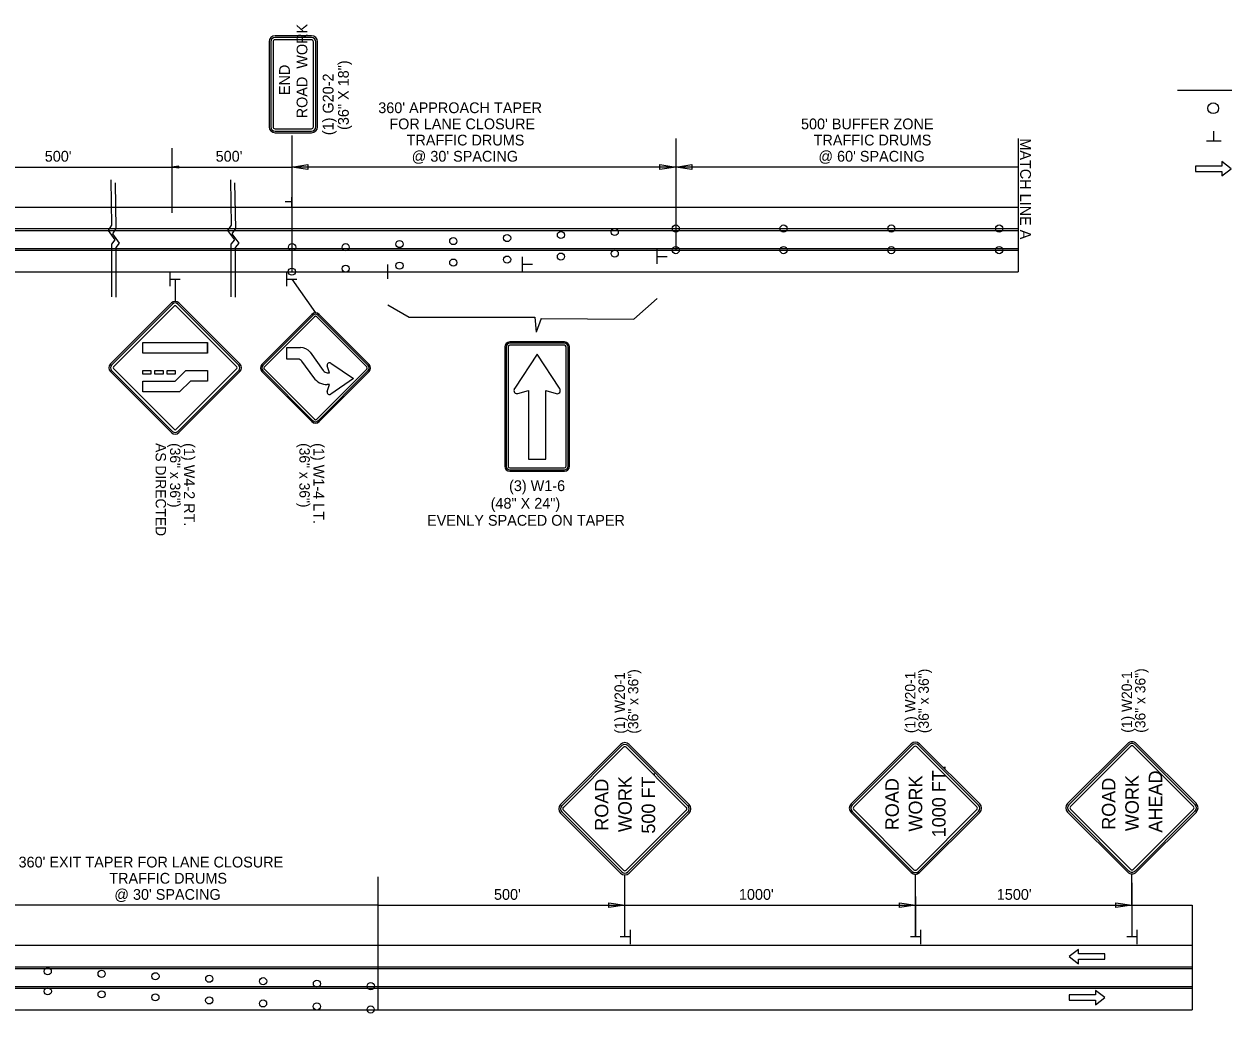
# Model space of a CAD drawing. Extents: x 1930579 to 1946213, y 596452 to 597784.
# Drawn here: x 1936788 to 1937455, y 597094 to 597644 of the extents above; entities that cross this region are included whole.
import ezdxf

# ---------------------------------------------------------------- set-up
doc = ezdxf.new("R2010")
doc.units = 0
for name, color, linetype in [('Default', 7, 'Continuous'), ('P_TC_Signs_Permanent', 7, 'Continuous'), ('P_TC_Signs_Temporary', 7, 'Continuous'), ('R_Border', 7, 'Continuous'), ('R_MOT', 7, 'Continuous'), ('R_Striping', 7, 'Continuous')]:
    doc.layers.add(name, color=color, linetype=linetype)

# ---------------------------------------------------------------- blocks, each defined once
blk = doc.blocks.new('W20-1')
at = {"layer": 'P_TC_Signs_Temporary'}
for p, q in [((-5.97, 6.53), (-0.4, 12.1)), ((-5.86, 6.42), (-0.29, 11.99)), ((-5.7, 6.26), (-0.13, 11.83)), ((0.13, 11.83), (5.7, 6.26)), ((0.29, 11.99), (5.86, 6.42)), ((0.4, 12.1), (5.97, 6.53)), ((-0.4, 0.16), (-5.97, 5.73)), ((-0.29, 0.28), (-5.86, 5.84)), ((-0.13, 0.43), (-5.7, 6)), ((5.7, 6), (0.13, 0.43)), ((5.86, 5.84), (0.29, 0.28)), ((5.97, 5.73), (0.4, 0.16))]:
    blk.add_line(p, q, dxfattribs=at)
for centre, radius, start, end in [((0, 11.7), 0.562, 45, 135), ((0, 11.7), 0.406, 45, 135), ((0, 11.7), 0.188, 45, 135), ((-5.57, 6.13), 0.562, 135, 225), ((-5.57, 6.13), 0.406, 135, 225), ((-5.57, 6.13), 0.187, 135, 225), ((5.57, 6.13), 0.187, 315, 45), ((5.57, 6.13), 0.406, 315, 45), ((5.57, 6.13), 0.562, 315, 45), ((0, 0.56), 0.562, 225, 315), ((0, 0.56), 0.406, 225, 315), ((0, 0.56), 0.188, 225, 315)]:
    blk.add_arc(centre, radius, start, end, dxfattribs=at)
for s, p in [(' ROAD ', (-2.5, 7.67)), ('WORK', (-2.16, 5.5)), (' AHEAD ', (-2.76, 3.33))]:
    blk.add_text(s, height=1.25, dxfattribs=at).set_placement(p)

msp = doc.modelspace()

# ---------------------------------------------------------------- linework, layer by layer
at = {"layer": 'Default'}
for p, q in [((1937150.32, 597580.59), (1937150.32, 597518.47)), ((1937340.86, 597580.59), (1937340.86, 597506.47)), ((1936869.84, 597575.24), (1936869.84, 597539.32)), ((1936936.62, 597575.24), (1936936.62, 597506.47)), ((1936749.27, 597564.71), (1936936.62, 597564.71)), ((1936873.67, 597565.28), (1936869.84, 597564.71)), ((1936869.84, 597564.71), (1936936.62, 597564.71)), ((1936873.67, 597564.13), (1936869.84, 597564.71)), ((1936873.67, 597565.19), (1936870.48, 597564.71)), ((1936873.67, 597564.23), (1936870.48, 597564.71)), ((1936873.67, 597565.09), (1936871.14, 597564.71)), ((1936873.67, 597564.33), (1936871.14, 597564.71)), ((1936873.67, 597564.99), (1936871.77, 597564.71)), ((1936873.67, 597564.42), (1936871.77, 597564.71)), ((1936873.67, 597564.89), (1936872.42, 597564.71)), ((1936873.67, 597564.52), (1936872.42, 597564.71)), ((1936873.67, 597564.8), (1936873.06, 597564.71)), ((1936873.67, 597564.62), (1936873.06, 597564.71)), ((1936873.67, 597564.13), (1936873.67, 597565.28)), ((1936936.62, 597564.71), (1936945.49, 597566.04)), ((1937303.84, 597564.71), (1936936.62, 597564.71)), ((1936945.49, 597563.38), (1936936.62, 597564.71)), ((1936945.49, 597566.04), (1936945.49, 597563.38)), ((1937141.45, 597563.38), (1937141.45, 597566.04)), ((1937141.45, 597566.04), (1937150.32, 597564.71)), ((1937150.32, 597564.71), (1937141.45, 597563.38)), ((1937150.32, 597564.71), (1937159.19, 597566.04)), ((1937159.19, 597563.38), (1937150.32, 597564.71)), ((1937159.19, 597566.04), (1937159.19, 597563.38)), ((1937340.86, 597564.71), (1937303.84, 597564.71)), ((1936936.54, 597545.34), (1936932.94, 597545.34)), ((1936936.62, 597542.72), (1936936.62, 597548)), ((1936407.68, 597542.47), (1937340.86, 597542.47)), ((1936407.68, 597530.47), (1937340.86, 597530.47)), ((1936407.68, 597529.47), (1937340.86, 597529.47)), ((1936407.68, 597519.47), (1937340.86, 597519.47)), ((1936407.68, 597518.47), (1937340.86, 597518.47)), ((1937139.89, 597510.89), (1937139.89, 597518.87)), ((1936990.13, 597502.48), (1936990.13, 597510.46)), ((1937065.01, 597506.69), (1937065.01, 597514.67)), ((1937065.13, 597510.66), (1937070.58, 597510.66)), ((1937140.01, 597514.86), (1937145.46, 597514.86)), ((1936407.68, 597506.47), (1937340.86, 597506.47)), ((1936868.85, 597498.34), (1936868.85, 597506.32)), ((1936933.78, 597498.34), (1936933.78, 597506.32)), ((1936990.25, 597506.45), (1936995.69, 597506.45)), ((1936868.97, 597502.31), (1936874.41, 597502.31)), ((1936933.9, 597502.31), (1936939.34, 597502.31)), ((1936984.52, 597169.77), (1936984.52, 597095.65)), ((1937404.18, 597166.28), (1937404.18, 597136.25)), ((1937283.73, 597158.78), (1937283.73, 597136.25)), ((1936984.52, 597153.89), (1936770.82, 597153.89)), ((1936984.52, 597153.89), (1937437.73, 597153.89)), ((1937113.15, 597152.56), (1937113.15, 597155.22)), ((1937113.15, 597155.22), (1937122.01, 597153.89)), ((1937122.01, 597153.89), (1937113.15, 597152.56)), ((1937274.86, 597152.56), (1937274.86, 597155.22)), ((1937274.86, 597155.22), (1937283.73, 597153.89)), ((1937283.73, 597153.89), (1937274.86, 597152.56)), ((1937395.31, 597152.56), (1937395.31, 597155.22)), ((1937395.31, 597155.22), (1937404.18, 597153.89)), ((1937404.18, 597153.89), (1937395.31, 597152.56)), ((1937437.73, 597153.89), (1937437.73, 597095.65)), ((1937124.76, 597136.27), (1937119.32, 597136.26)), ((1937124.88, 597140.24), (1937124.88, 597132.26)), ((1937286.33, 597136.31), (1937280.88, 597136.31)), ((1937286.45, 597140.28), (1937286.45, 597132.3)), ((1937406.79, 597136.27), (1937401.34, 597136.27)), ((1937406.9, 597140.24), (1937406.9, 597132.26)), ((1936437.73, 597131.65), (1937437.73, 597131.65)), ((1936437.73, 597119.65), (1937437.73, 597119.65)), ((1936437.73, 597119.65), (1936984.52, 597119.65)), ((1936437.73, 597118.65), (1937437.73, 597118.65)), ((1936437.73, 597108.65), (1937437.73, 597108.65)), ((1936437.73, 597107.65), (1937437.73, 597107.65)), ((1936437.73, 597095.65), (1937437.73, 597095.65))]:
    msp.add_line(p, q, dxfattribs=at)
for points in [[(1936835.94, 597557.58), (1936836.33, 597532.34), (1936834.38, 597529.45), (1936838.17, 597524.25), (1936836.18, 597521.85), (1936836.17, 597492.5)], [(1936902.4, 597557.58), (1936902.78, 597532.34), (1936900.83, 597529.45), (1936904.63, 597524.25), (1936902.63, 597521.85), (1936902.63, 597492.5)], [(1936838.33, 597555.98), (1936838.72, 597530.42), (1936836.77, 597527.52), (1936840.57, 597522.32), (1936838.57, 597519.92), (1936838.57, 597492.36)], [(1936904.79, 597555.98), (1936905.18, 597530.42), (1936903.23, 597527.52), (1936907.03, 597522.32), (1936905.03, 597519.92), (1936905.02, 597492.36)]]:
    msp.add_lwpolyline(points, dxfattribs=at)
for centre, radius in [((1937449.45, 597597.42), 3), ((1937116.34, 597528.57), 1.99), ((1937150.32, 597530.47), 1.99), ((1937210.32, 597530.47), 1.99), ((1937270.32, 597530.47), 1.99), ((1937330.32, 597530.47), 1.99), ((1936996.53, 597521.84), 1.99), ((1937026.48, 597523.52), 1.99), ((1937056.43, 597525.2), 1.99), ((1937086.39, 597526.88), 1.99), ((1936936.78, 597520.13), 1.99), ((1936966.57, 597520.16), 1.99), ((1937086.39, 597514.88), 1.99), ((1937116.34, 597516.57), 1.99), ((1937150.32, 597518.47), 1.99), ((1937210.32, 597518.47), 1.99), ((1937270.32, 597518.47), 1.99), ((1937330.32, 597518.47), 1.99), ((1936966.57, 597508.16), 1.99), ((1936996.53, 597509.84), 1.99), ((1937026.48, 597511.52), 1.99), ((1937056.43, 597513.2), 1.99), ((1936936.62, 597506.47), 1.99), ((1936800.75, 597117.08), 1.99), ((1936830.72, 597115.71), 1.99), ((1936860.69, 597114.34), 1.99), ((1936890.66, 597112.97), 1.99), ((1936920.63, 597111.59), 1.99), ((1936950.59, 597110.22), 1.99), ((1936980.56, 597108.85), 1.99), ((1936800.78, 597105.97), 1.99), ((1936830.73, 597104.29), 1.99), ((1936860.68, 597102.61), 1.99), ((1936890.64, 597100.93), 1.99), ((1936920.59, 597099.24), 1.99), ((1936950.54, 597097.56), 1.99), ((1936980.49, 597095.88), 1.99)]:
    msp.add_circle(centre, radius, dxfattribs=at)
at = {"layer": 'P_TC_Signs_Permanent'}
for p, q in [((1936835.63, 597455.14), (1936869.57, 597489.08)), ((1936919.98, 597454.85), (1936947.82, 597482.69)), ((1936920.51, 597454.32), (1936948.35, 597482.16)), ((1936949.15, 597481.36), (1936921.31, 597453.52)), ((1936978.32, 597453.52), (1936950.47, 597481.36)), ((1936951.27, 597482.16), (1936979.11, 597454.32)), ((1936951.8, 597482.69), (1936979.64, 597454.85)), ((1936889.69, 597461.06), (1936889.69, 597467.06)), ((1937055.13, 597464.56), (1937055.13, 597398.19)), ((1937055.88, 597464.56), (1937055.88, 597398.19)), ((1937057.01, 597464.56), (1937057.01, 597398.19)), ((1937088.32, 597467.38), (1937057.95, 597467.38)), ((1937088.32, 597466.63), (1937057.95, 597466.63)), ((1937088.32, 597465.5), (1937057.95, 597465.5)), ((1937089.26, 597398.19), (1937089.26, 597464.56)), ((1937090.38, 597398.19), (1937090.38, 597464.56)), ((1937091.13, 597398.19), (1937091.13, 597464.56)), ((1936948.77, 597447.57), (1936942.25, 597456.61)), ((1936946.73, 597461.62), (1936954.09, 597451.4)), ((1936869.57, 597416.95), (1936835.63, 597450.9)), ((1936907.75, 597450.9), (1936873.81, 597416.95)), ((1936947.82, 597423.03), (1936919.98, 597450.87)), ((1936948.35, 597423.56), (1936920.51, 597451.4)), ((1936921.31, 597452.2), (1936949.15, 597424.35)), ((1936950.47, 597424.35), (1936978.32, 597452.2)), ((1936979.11, 597451.4), (1936951.27, 597423.56)), ((1936979.64, 597450.87), (1936951.8, 597423.03)), ((1937057.95, 597397.25), (1937088.32, 597397.25)), ((1937057.95, 597396.13), (1937088.32, 597396.13)), ((1937057.95, 597395.38), (1937088.32, 597395.38))]:
    msp.add_line(p, q, dxfattribs=at)
for points in [[(1936870.2, 597488.44), (1936836.26, 597454.5)], [(1936837.32, 597453.44), (1936871.26, 597487.38)], [(1936872.11, 597487.38), (1936906.05, 597453.44)], [(1936907.11, 597454.5), (1936873.17, 597488.44)], [(1936873.81, 597489.08), (1936890.78, 597472.11), (1936907.75, 597455.14)], [(1936939.97, 597457.78), (1936933.87, 597457.78), (1936933.87, 597464.34), (1936941.41, 597464.34)], [(1937085.58, 597441.63), (1937073.13, 597460.63), (1937060.73, 597441.62)], [(1936836.26, 597451.53), (1936870.2, 597417.59)], [(1936871.26, 597418.65), (1936837.32, 597452.59)], [(1936906.05, 597452.59), (1936872.11, 597418.65)], [(1936873.17, 597417.59), (1936907.11, 597451.53)], [(1936956.37, 597450.23), (1936957.57, 597450.23), (1936956.34, 597454.05)], [(1936958.33, 597455.54), (1936970.91, 597446.95), (1936958.33, 597438.37)], [(1936956.34, 597439.85), (1936957.57, 597443.67), (1936956.37, 597443.67)], [(1937062.5, 597438.67), (1937068.26, 597440.39), (1937068.26, 597402.13), (1937078.01, 597402.13), (1937078.01, 597440.39), (1937083.76, 597438.64)]]:
    msp.add_lwpolyline(points, dxfattribs=at)
for points in [[(1936853.69, 597461.06), (1936853.69, 597467.06), (1936889.69, 597467.06), (1936889.69, 597461.06)], [(1936853.69, 597449.42), (1936853.69, 597451.52), (1936858.19, 597451.52), (1936858.19, 597449.42)], [(1936853.69, 597439.52), (1936853.69, 597445.52), (1936871.69, 597445.52), (1936877.69, 597451.52), (1936889.69, 597451.52), (1936889.69, 597445.52), (1936880.17, 597445.52), (1936874.17, 597439.52)], [(1936860.44, 597449.42), (1936860.44, 597451.52), (1936864.94, 597451.52), (1936864.94, 597449.42)], [(1936867.19, 597449.42), (1936867.19, 597451.52), (1936871.69, 597451.52), (1936871.69, 597449.42)]]:
    msp.add_lwpolyline(points, close=True, dxfattribs=at)
for centre, radius, start, end in [((1936871.69, 597486.96), 3, 45, 135), ((1936871.69, 597486.96), 2.1, 45, 135), ((1936871.69, 597486.96), 0.6, 45, 135), ((1936949.81, 597480.7), 2.81, 45, 135), ((1936949.81, 597480.7), 2.06, 45, 135), ((1936949.81, 597480.7), 0.938, 45, 135), ((1936941.41, 597457.78), 6.56, 35.77329, 90), ((1937057.95, 597464.56), 2.81, 90, 180), ((1937057.95, 597464.56), 2.06, 90, 180), ((1937057.95, 597464.56), 0.938, 90, 180), ((1937088.32, 597464.56), 2.81, 360, 90), ((1937088.32, 597464.56), 2.06, 360, 90), ((1937088.32, 597464.56), 0.938, 360, 90), ((1936939.97, 597454.97), 2.81, 35.77329, 90), ((1936837.75, 597453.02), 3, 135, 225), ((1936837.75, 597453.02), 2.1, 135, 225), ((1936837.75, 597453.02), 0.6, 135, 225), ((1936905.63, 597453.02), 0.6, 315, 45), ((1936905.63, 597453.02), 2.1, 315, 45), ((1936905.63, 597453.02), 3, 315, 45), ((1936921.97, 597452.86), 2.81, 135, 225), ((1936921.97, 597452.86), 2.06, 135, 225), ((1936921.97, 597452.86), 0.937, 135, 225), ((1936956.37, 597453.05), 2.81, 215.77329, 270), ((1936957.59, 597454.45), 1.31, 55.6763, 197.81282), ((1936977.65, 597452.86), 0.938, 315, 45), ((1936977.65, 597452.86), 2.06, 315, 45), ((1936977.65, 597452.86), 2.81, 315, 45), ((1936956.37, 597453.05), 9.38, 215.77329, 270), ((1936957.59, 597439.45), 1.31, 162.18718, 304.3237), ((1937062.01, 597440.37), 1.76, 146.59943, 285.96908), ((1936997.93, 597482.63), 75, 326.59943, 326.85697), ((1937084.25, 597440.37), 1.8, 254.03093, 33.47548), ((1937148.31, 597482.73), 75, 213.2286, 213.47548), ((1936949.81, 597425.02), 2.06, 225, 315), ((1936949.81, 597425.02), 0.938, 225, 315), ((1936871.69, 597419.08), 3, 225, 315), ((1936871.69, 597419.08), 2.1, 225, 315), ((1936871.69, 597419.08), 0.6, 225, 315), ((1936949.81, 597425.02), 2.81, 225, 315), ((1937057.95, 597398.19), 2.81, 180, 270), ((1937057.95, 597398.19), 2.06, 180, 270), ((1937057.95, 597398.19), 0.937, 180, 270), ((1937088.32, 597398.19), 2.81, 270, 360), ((1937088.32, 597398.19), 2.06, 270, 360), ((1937088.32, 597398.19), 0.938, 270, 360)]:
    msp.add_arc(centre, radius, start, end, dxfattribs=at)
at = {"layer": 'P_TC_Signs_Temporary'}
for p, q in [((1936947.54, 597637.78), (1936927.29, 597637.78)), ((1936947.54, 597636.84), (1936927.29, 597636.84)), ((1936923.92, 597634.41), (1936923.92, 597587.16)), ((1936924.85, 597634.41), (1936924.85, 597587.16)), ((1936926.17, 597634.41), (1936926.17, 597587.16)), ((1936947.54, 597635.53), (1936927.29, 597635.53)), ((1936948.67, 597587.16), (1936948.67, 597634.41)), ((1936949.98, 597587.16), (1936949.98, 597634.41)), ((1936950.92, 597587.16), (1936950.92, 597634.41)), ((1936927.29, 597586.03), (1936947.54, 597586.03)), ((1936927.29, 597584.72), (1936947.54, 597584.72)), ((1936927.29, 597583.78), (1936947.54, 597583.78)), ((1937086.19, 597209.95), (1937119.6, 597243.37)), ((1937124.37, 597243.37), (1937157.78, 597209.95)), ((1937247.88, 597210.25), (1937281.29, 597243.66)), ((1937248.54, 597209.59), (1937281.95, 597243)), ((1937285.4, 597243), (1937318.81, 597209.59)), ((1937286.06, 597243.66), (1937319.48, 597210.25)), ((1937086.85, 597209.29), (1937120.26, 597242.7)), ((1937087.78, 597208.36), (1937121.19, 597241.77)), ((1937122.78, 597241.77), (1937156.19, 597208.36)), ((1937123.71, 597242.7), (1937157.12, 597209.29)), ((1937249.47, 597208.66), (1937282.88, 597242.07)), ((1937284.47, 597242.07), (1937317.88, 597208.66)), ((1937119.6, 597171.77), (1937086.19, 597205.18)), ((1937120.26, 597172.43), (1937086.85, 597205.84)), ((1937121.19, 597173.36), (1937087.78, 597206.77)), ((1937156.19, 597206.77), (1937122.78, 597173.36)), ((1937157.12, 597205.84), (1937123.71, 597172.43)), ((1937157.78, 597205.18), (1937124.37, 597171.77)), ((1937281.29, 597172.07), (1937247.88, 597205.48)), ((1937281.95, 597172.73), (1937248.54, 597206.14)), ((1937282.88, 597173.66), (1937249.47, 597207.07)), ((1937317.88, 597207.07), (1937284.47, 597173.66)), ((1937318.81, 597206.14), (1937285.4, 597172.73)), ((1937319.48, 597205.48), (1937286.06, 597172.07))]:
    msp.add_line(p, q, dxfattribs=at)
for centre, radius, start, end in [((1936927.29, 597634.41), 3.38, 90, 180), ((1936927.29, 597634.41), 2.44, 90, 180), ((1936947.54, 597634.41), 3.37, 360, 90), ((1936947.54, 597634.41), 2.44, 360, 90), ((1936927.29, 597634.41), 1.13, 90, 180), ((1936947.54, 597634.41), 1.13, 360, 90), ((1936927.29, 597587.16), 3.37, 180, 270), ((1936927.29, 597587.16), 2.44, 180, 270), ((1936927.29, 597587.16), 1.13, 180, 270), ((1936947.54, 597587.16), 2.44, 270, 360), ((1936947.54, 597587.16), 1.13, 270, 360), ((1936947.54, 597587.16), 3.37, 270, 360), ((1937121.99, 597240.98), 3.38, 45, 135), ((1937121.99, 597240.98), 2.44, 45, 135), ((1937283.68, 597241.27), 3.38, 45, 135), ((1937283.68, 597241.27), 2.44, 45, 135), ((1937121.99, 597240.98), 1.12, 45, 135), ((1937283.68, 597241.27), 1.12, 45, 135), ((1937088.58, 597207.57), 3.38, 135, 225), ((1937155.4, 597207.57), 3.38, 315, 45), ((1937250.27, 597207.86), 3.38, 135, 225), ((1937250.27, 597207.86), 2.44, 135, 225), ((1937317.09, 597207.86), 2.44, 315, 45), ((1937317.09, 597207.86), 3.38, 315, 45), ((1937088.58, 597207.57), 2.44, 135, 225), ((1937088.58, 597207.57), 1.13, 135, 225), ((1937155.4, 597207.57), 1.13, 315, 45), ((1937155.4, 597207.57), 2.44, 315, 45), ((1937250.27, 597207.86), 1.13, 135, 225), ((1937317.09, 597207.86), 1.13, 315, 45), ((1937121.99, 597174.16), 3.38, 225, 315), ((1937121.99, 597174.16), 2.44, 225, 315), ((1937121.99, 597174.16), 1.12, 225, 315), ((1937283.68, 597174.45), 3.38, 225, 315), ((1937283.68, 597174.45), 2.44, 225, 315), ((1937283.68, 597174.45), 1.12, 225, 315)]:
    msp.add_arc(centre, radius, start, end, dxfattribs=at)
at = {"layer": 'R_Border'}
for p, q in [((1937429.67, 597607.45), (1937623.59, 597607.59)), ((1937449.83, 597579.25), (1937449.83, 597584.71)), ((1936936.62, 597582.19), (1936936.62, 597548)), ((1937453.81, 597579.14), (1937445.81, 597579.13)), ((1936871.69, 597502.31), (1936871.69, 597489.96)), ((1936936.62, 597502.31), (1936949.81, 597483.51)), ((1937127.05, 597480.04), (1937139.89, 597491.53)), ((1936990.13, 597488.05), (1937001.94, 597481.1)), ((1937001.94, 597481.1), (1937071.9, 597481.1)), ((1937071.9, 597481.1), (1937072.59, 597472.76)), ((1937075.37, 597480.41), (1937072.59, 597472.76)), ((1937075.37, 597480.41), (1937127.05, 597480.04)), ((1937122.04, 597136.27), (1937121.99, 597170.78)), ((1937283.73, 597136.56), (1937283.68, 597171.03)), ((1937404.3, 597136.27), (1937404.25, 597171.21))]:
    msp.add_line(p, q, dxfattribs=at)
at = {"layer": 'R_MOT'}
msp.add_lwpolyline([(1937454.33, 597559.74), (1937459.51, 597563.74), (1937454.32, 597567.74), (1937454.32, 597565.24), (1937439.61, 597565.23), (1937439.61, 597562.23), (1937454.32, 597562.24)], close=True, dxfattribs=at)
at = {"layer": 'R_Striping'}
for points in [[(1937374.48, 597129.28), (1937369.29, 597125.28), (1937374.48, 597121.28), (1937374.48, 597123.78), (1937389.2, 597123.78), (1937389.2, 597126.78), (1937374.48, 597126.78)], [(1937384, 597098.47), (1937389.2, 597102.47), (1937384, 597106.47), (1937384, 597103.97), (1937369.29, 597103.97), (1937369.29, 597100.97), (1937384, 597100.97)]]:
    msp.add_lwpolyline(points, close=True, dxfattribs=at)

# ---------------------------------------------------------------- block references
at = {"layer": 'Default', "xscale": 6, "yscale": 6, "rotation": 89.99999999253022}
msp.add_blockref('W20-1', (1937441.03, 597208.08), dxfattribs=at)

# ---------------------------------------------------------------- texts
at = {"layer": 'Default'}
for s, rotation, p in [("360' APPROACH TAPER ", 360, (1936984.72, 597594.71)), ('FOR LANE CLOSURE', 360, (1936990.88, 597585.71)), ("500' BUFFER ZONE", 360, (1937220.02, 597585.71)), ('TRAFFIC DRUMS', 360, (1937000.52, 597576.71)), ('TRAFFIC DRUMS', 360, (1937227.06, 597576.71)), ('MATCH LINE A', 270, (1937342, 597580.66)), ("500'", 360, (1936799.09, 597567.71)), ("500'", 360, (1936894.21, 597567.71)), ("@ 30' SPACING", 360, (1937003.33, 597567.71)), ("@ 60' SPACING", 360, (1937229.73, 597567.71)), ("360' EXIT TAPER FOR LANE CLOSURE", 360, (1936784.5, 597174.89)), ('TRAFFIC DRUMS', 360, (1936835.01, 597165.89)), ("@ 30' SPACING", 360, (1936837.82, 597156.89)), ("500'", 360, (1937049.14, 597156.89)), ("1000'", 360, (1937185.46, 597156.89)), ("1500'", 360, (1937329.01, 597156.89))]:
    msp.add_text(s, height=6, rotation=rotation, dxfattribs=at).set_placement(p)
at = {"layer": 'P_TC_Signs_Temporary'}
for s, height, p in [('ROAD  WORK', 6, (1936945.29, 597591.82)), ('END', 6, (1936935.54, 597604.75)), ('1000 FT.', 7.5, (1937300.51, 597191.69)), (' ROAD ', 7.5, (1937112.77, 597192.55)), ('WORK', 7.5, (1937125.8, 597194.58)), ('500 FT.', 7.5, (1937138.82, 597193.73)), (' ROAD ', 7.5, (1937274.47, 597192.84)), ('WORK', 7.5, (1937287.49, 597194.87))]:
    msp.add_text(s, height=height, rotation=90, dxfattribs=at).set_placement(p)
at = {"layer": 'R_Border'}
for s, height, rotation, p in [('(36" X 18")', 6, 90, (1936968.32, 597585.37)), ('(1) G20-2', 6, 90, (1936959.81, 597582.44)), ('AS DIRECTED ', 5.76, 270, (1936860.8, 597411.08)), ('(36" x 36")', 5.76, 270, (1936868.81, 597411.08)), ('(1) W4-2 RT.', 6, 270, (1936876.58, 597411.08)), ('(36" x 36")', 5.76, 270, (1936940.85, 597411.08)), ('(1) W1-4 LT.', 6, 270, (1936948.62, 597411.08)), ('(3) W1-6', 6, 0.00754, (1937057.52, 597384.37)), ('(48" X 24")', 6, 0.00754, (1937047.29, 597374.57)), ('EVENLY SPACED ON TAPER', 6, 0.00754, (1937011.88, 597365.08)), ('(1) W20-1', 5.76, 90, (1937121.99, 597249.35)), ('(36" x 36")', 5.76, 90, (1937129.48, 597249.35)), ('(1) W20-1', 5.76, 90, (1937283.68, 597249.65)), ('(36" x 36")', 5.76, 90, (1937291.17, 597249.65)), ('(1) W20-1', 5.76, 90, (1937404.24, 597249.86)), ('(36" x 36")', 5.76, 90, (1937411.73, 597249.86))]:
    msp.add_text(s, height=height, rotation=rotation, dxfattribs=at).set_placement(p)

doc.saveas('drawing.dxf')
